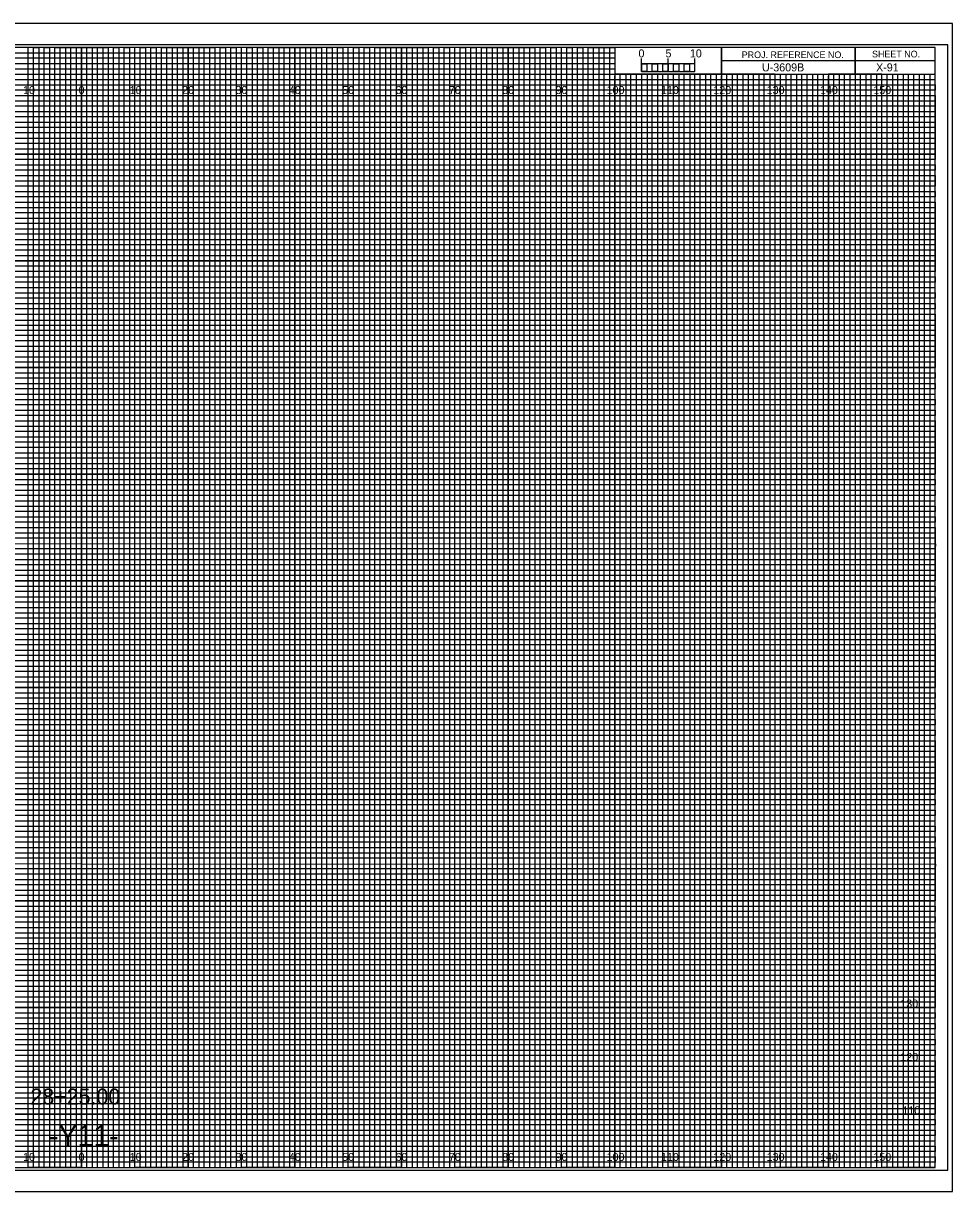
# Model space of a CAD drawing. Extents: x -13 to 323, y -5 to 3294.
# Drawn here: x 149.1 to 323.3, y 3075.5 to 3294.5 of the extents above; entities that cross this region are included whole.
import ezdxf

# ---------------------------------------------------------------- set-up
doc = ezdxf.new("R2010")
doc.units = 0
for name, color, linetype in [('Prop XS Alignment Label', 7, 'Continuous'), ('Prop XS Bar Scale Labels', 7, 'Continuous'), ('Prop XS Elevation Labels', 7, 'Continuous'), ('Prop XS Offset Labels', 7, 'Continuous'), ('Prop XS Project Number', 7, 'Continuous'), ('Prop XS Sheet Number', 7, 'Continuous'), ('Prop XS Station Labels', 7, 'Continuous'), ('Sheet Cross Section CELL', 7, 'Continuous'), ('Sheet Cross Section Grid Major CELL', 7, 'Continuous'), ('Sheet Cross Section Grid Middle CELL', 7, 'Continuous'), ('Sheet Cross Section Grid Minor 1 CELL', 7, 'Continuous'), ('Sheet Cross Section Grid Minor 2 CELL', 7, 'Continuous'), ('Sheet Cross Section Scale CELL', 7, 'Continuous'), ('Sheet Cutting Line CELL', 7, 'Continuous'), ('Sheet DOT Grid CELL', 7, 'Continuous'), ('Sheet Plot Border Inside CELL', 7, 'Continuous'), ('Sheet Plot Border Outside CELL', 7, 'Continuous')]:
    doc.layers.add(name, color=color, linetype=linetype)

msp = doc.modelspace()

# ---------------------------------------------------------------- linework, layer by layer
at = {"layer": 'Sheet Cross Section CELL'}
for p, q in [((305, 3290), (305, 3285)), ((305, 3285), (305, 3290)), ((280, 3287.5), (280, 3285)), ((320, 3287.49), (280, 3287.49)), ((280, 3285), (320, 3285))]:
    msp.add_line(p, q, dxfattribs=at)
for points in [[(320, 3290), (0, 3290), (0, 3080), (320, 3080)], [(280, 3290), (260, 3290), (260, 3285.03), (280, 3285.03)], [(320, 3290), (280, 3290), (280, 3285), (320, 3285)]]:
    msp.add_lwpolyline(points, close=True, dxfattribs=at)
at = {"layer": 'Sheet Cross Section Grid Major CELL'}
for p, q in [((150, 3290), (140, 3290)), ((150, 3080), (150, 3290)), ((170, 3290), (160, 3290)), ((160, 3290), (160, 3080)), ((170, 3080), (170, 3290)), ((190, 3290), (180, 3290)), ((180, 3290), (180, 3080)), ((190, 3080), (190, 3290)), ((210, 3290), (200, 3290)), ((200, 3290), (200, 3080)), ((210, 3080), (210, 3290)), ((230, 3290), (220, 3290)), ((220, 3290), (220, 3080)), ((230, 3080), (230, 3290)), ((250, 3290), (240, 3290)), ((240, 3290), (240, 3080)), ((250, 3080), (250, 3290)), ((260, 3290), (260, 3080)), ((270, 3080), (270, 3285)), ((290, 3285), (280, 3285)), ((280, 3285), (280, 3080)), ((290, 3080), (290, 3285)), ((310, 3285), (300, 3285)), ((300, 3285), (300, 3080)), ((310, 3080), (310, 3285)), ((160, 3080), (150, 3080)), ((180, 3080), (170, 3080)), ((200, 3080), (190, 3080)), ((220, 3080), (210, 3080)), ((240, 3080), (230, 3080)), ((260, 3080), (250, 3080)), ((280, 3080), (270, 3080)), ((300, 3080), (290, 3080)), ((320, 3080), (310, 3080)), ((320, 3080), (320, 3080))]:
    msp.add_line(p, q, dxfattribs=at)
for points in [[(0, 3280), (320, 3280), (320, 3270), (0, 3270)], [(0, 3260), (320, 3260), (320, 3250), (0, 3250)], [(0, 3240), (320, 3240), (320, 3230), (0, 3230)], [(0, 3220), (320, 3220), (320, 3210), (0, 3210)], [(0, 3200), (320, 3200), (320, 3190), (0, 3190)], [(0, 3180), (320, 3180), (320, 3170), (0, 3170)], [(0, 3160), (320, 3160), (320, 3150), (0, 3150)], [(0, 3140), (320, 3140), (320, 3130), (0, 3130)], [(0, 3120), (320, 3120), (320, 3110), (0, 3110)], [(0, 3100), (320, 3100), (320, 3090), (0, 3090)]]:
    msp.add_lwpolyline(points, dxfattribs=at)
at = {"layer": 'Sheet Cross Section Grid Middle CELL'}
for points in [[(145, 3080), (155, 3080), (155, 3290), (165, 3290), (165, 3080), (175, 3080), (175, 3290), (185, 3290), (185, 3080), (195, 3080), (195, 3290), (205, 3290), (205, 3080), (215, 3080), (215, 3290), (225, 3290), (225, 3080), (235, 3080), (235, 3290), (245, 3290), (245, 3080), (255, 3080), (255, 3290), (259.93, 3290), (260, 3290), (260, 3285), (264.99, 3285), (264.99, 3080), (275, 3080), (275, 3285), (285, 3285), (285, 3080), (295, 3080), (295, 3285), (305, 3285), (305, 3080), (315, 3080), (315, 3285)], [(0, 3285), (275, 3285)], [(0, 3265), (320, 3265), (320, 3275), (0, 3275)], [(0, 3245), (320, 3245), (320, 3255), (0, 3255)], [(0, 3225), (320, 3225), (320, 3235), (0, 3235)], [(0, 3205), (320, 3205), (320, 3215), (0, 3215)], [(0, 3185), (320, 3185), (320, 3195), (0, 3195)], [(0, 3165), (320, 3165), (320, 3175), (0, 3175)], [(0, 3145), (320, 3145), (320, 3155), (0, 3155)], [(0, 3125), (320, 3125), (320, 3135), (0, 3135)], [(0, 3105), (320, 3105), (320, 3115), (0, 3115)], [(0, 3085), (320, 3085), (320, 3095), (0, 3095)]]:
    msp.add_lwpolyline(points, dxfattribs=at)
at = {"layer": 'Sheet Cross Section Grid Minor 1 CELL'}
for p, q in [((0, 3289), (260, 3289)), ((260, 3287.98), (0, 3287.98)), ((260, 3289), (260, 3287.98)), ((0, 3287), (260, 3287)), ((260, 3285.89), (0, 3285.89)), ((260, 3287), (260, 3285.89)), ((0, 3284), (320, 3284))]:
    msp.add_line(p, q, dxfattribs=at)
for points in [[(0, 3283), (270, 3283), (320, 3283), (320, 3282), (0, 3282)], [(0, 3281), (320, 3281), (320, 3279), (0, 3279)], [(0, 3278), (320, 3278), (320, 3277), (0, 3276.98)], [(0, 3276), (320, 3276), (320, 3274), (0, 3274)], [(0, 3273), (320, 3273), (320, 3272), (0, 3272)], [(0, 3271), (320, 3271), (320, 3269), (0, 3269)], [(0, 3268), (320, 3268), (320, 3267), (0, 3267)], [(0, 3266), (320, 3266), (320, 3264), (0, 3264)], [(0, 3263), (320, 3263), (320, 3262), (0, 3262)], [(0, 3261), (320, 3261), (320, 3259), (0, 3259)], [(0, 3258), (320, 3258), (320, 3257), (0, 3257)], [(0, 3256), (320, 3256), (320, 3253.95), (320, 3253), (320, 3252), (0, 3252)], [(0, 3254), (320, 3254), (320, 3253), (0, 3253)], [(0, 3251), (320, 3251), (320, 3249), (0, 3249.03)], [(0, 3249.03), (320, 3249), (320, 3248), (0, 3248)], [(0, 3247), (320, 3247), (320, 3246), (0, 3246)], [(0, 3244), (320, 3244), (320, 3243), (0, 3243)], [(0, 3242), (320, 3242), (320, 3241), (0, 3241)], [(-0.07, 3238.89), (320, 3238.89), (320, 3237.88), (-0.07, 3237.88)], [(0, 3237), (320, 3237), (320, 3236), (0, 3236)], [(0, 3234), (320, 3234), (320, 3233), (0, 3233)], [(0, 3232), (320, 3232), (320, 3231), (0, 3231)], [(0, 3229), (320, 3229), (320, 3228), (0, 3228)], [(0, 3227), (320, 3227), (320, 3226), (0, 3226)], [(0, 3224), (320, 3224), (320, 3223), (0, 3223)], [(0, 3222), (320, 3222), (320, 3221), (0, 3221)], [(0, 3219), (320, 3219), (319.99, 3217.98), (0, 3218)], [(0, 3217), (320, 3217), (320, 3216), (0, 3216)], [(0, 3214), (320, 3214), (320, 3213), (0, 3213)], [(0, 3212), (320, 3212), (320, 3211), (0, 3211)], [(0, 3209), (320, 3209), (320, 3208), (0, 3208)], [(0, 3207), (320, 3207), (320, 3206), (0, 3206)], [(0, 3204), (320, 3204), (320, 3203), (0, 3203)], [(0, 3202), (320, 3202), (320, 3201), (0, 3201)], [(0, 3199), (320, 3199), (320, 3198), (0, 3198)], [(0, 3196.99), (320.07, 3196.91), (320, 3196), (0, 3196)], [(0, 3194), (320, 3194), (320, 3193), (0, 3193)], [(0, 3192), (320, 3192), (320, 3191), (0, 3191)], [(0, 3189), (320, 3189), (320, 3188), (0, 3188)], [(0, 3187), (320, 3187), (320, 3186), (0, 3186)], [(0, 3184), (320, 3184), (320, 3183), (0, 3183)], [(0, 3182), (320, 3182), (320, 3181), (0, 3181)], [(0, 3179), (320, 3179), (320, 3178), (0, 3178)], [(0, 3177), (320, 3177), (320, 3176), (0, 3176)], [(0, 3174), (320, 3174), (320, 3173), (0, 3173)], [(0, 3172), (320, 3172), (320, 3171), (0, 3171)], [(0, 3169), (320, 3169), (320, 3168), (0, 3168)], [(0, 3167), (320, 3167), (320, 3166), (0, 3166)], [(0, 3164), (320, 3164), (320, 3163), (0, 3163)], [(0, 3162), (320, 3162), (320, 3161), (0, 3161)], [(0, 3159), (320, 3159), (319.99, 3157.98), (0, 3158)], [(0, 3157), (320, 3157), (320, 3156), (0, 3156)], [(0, 3154), (320, 3154), (320, 3153), (0, 3153)], [(0, 3152), (320, 3152), (320, 3151), (0, 3151)], [(0, 3149), (320, 3149), (320, 3148), (0, 3148)], [(0, 3147), (320, 3147), (320, 3146), (0, 3146)], [(0, 3144), (320, 3144), (320, 3143), (0, 3143)], [(0, 3142), (320, 3142), (320, 3141), (0, 3141)], [(0, 3139), (320, 3139), (320, 3138), (0, 3138)], [(0, 3136.99), (320.07, 3136.91), (320, 3136), (0, 3136)], [(0, 3134), (320, 3134), (320, 3133), (0, 3133)], [(0, 3132), (320, 3132), (320, 3131), (0, 3131)], [(0, 3129), (320, 3129), (320, 3128), (0, 3128)], [(0, 3127), (320, 3127), (320, 3126), (0, 3126)], [(0, 3124), (320, 3124), (320, 3123), (0, 3123)], [(0, 3122), (320, 3122), (320, 3121), (0, 3121)], [(0, 3119), (320, 3119), (320, 3118), (0, 3118)], [(0, 3117), (320, 3117), (320, 3116), (0, 3116)], [(0, 3114), (320, 3114), (320, 3113), (0, 3113)], [(0, 3112), (320, 3112), (320, 3111), (0, 3111)], [(0, 3109), (320, 3109), (320, 3108), (0, 3108)], [(0, 3107), (320, 3107), (320, 3106), (0, 3106)], [(0, 3104), (320, 3104), (320, 3103), (0, 3103)], [(0, 3102), (320, 3102), (320, 3101), (0, 3101)], [(0, 3099), (320, 3099), (320, 3098), (0, 3098)], [(0, 3097), (320, 3097), (320, 3096), (0, 3096)], [(0, 3094), (320, 3094), (320, 3093), (0, 3093)], [(0, 3092), (320, 3092), (320, 3091), (0, 3091)], [(0, 3089), (320, 3089), (320, 3088), (0, 3088)], [(0, 3087), (320, 3087), (320, 3086), (0, 3086)], [(0, 3084), (320, 3084), (320, 3083), (0, 3083)], [(0, 3082), (320, 3082), (320, 3081), (0, 3081)]]:
    msp.add_lwpolyline(points, dxfattribs=at)
at = {"layer": 'Sheet Cross Section Grid Minor 2 CELL'}
for p, q in [((267, 3285), (266.01, 3285)), ((266.01, 3285), (266.01, 3080)), ((267, 3080), (267, 3285)), ((269, 3285), (268, 3285)), ((268, 3285), (268, 3080)), ((269, 3080), (269, 3285)), ((266.01, 3080), (265, 3080)), ((268, 3080), (267, 3080))]:
    msp.add_line(p, q, dxfattribs=at)
for points in [[(150, 3080), (151, 3080), (151, 3290), (152, 3290), (152, 3080)], [(152, 3080), (153, 3080), (153, 3290), (154, 3290), (154, 3080)], [(155, 3080), (156, 3080), (156, 3290), (157, 3290), (157, 3080)], [(157, 3080), (158, 3080), (158, 3290), (159, 3290), (159, 3080)], [(160, 3080), (161, 3080), (161, 3290), (162, 3290), (162, 3080)], [(162, 3080), (163, 3080), (163, 3290), (164, 3290), (164, 3080)], [(165, 3080), (166, 3080), (166, 3290), (167, 3290), (167, 3080)], [(167, 3080), (168, 3080), (168, 3290), (169, 3290), (169, 3080)], [(170, 3080), (171, 3080), (171, 3290), (172, 3290), (172, 3080)], [(172, 3080), (173, 3080), (173, 3290), (174, 3290), (174, 3080)], [(175, 3080), (176, 3080), (176, 3290), (177, 3290), (177, 3080)], [(177, 3080), (178, 3080), (178, 3290), (179, 3290), (179, 3080)], [(180, 3080), (181, 3080), (181, 3290), (182, 3290), (182, 3080)], [(182, 3080), (183, 3080), (183, 3290), (184, 3290), (184, 3080)], [(185, 3080), (186, 3080), (186, 3290), (187, 3290), (187, 3080)], [(187, 3080), (188, 3080), (188, 3290), (189, 3290), (189, 3080)], [(190, 3080), (191, 3080), (191, 3290), (192, 3290), (192, 3080)], [(192, 3080), (193, 3080), (193, 3290), (194, 3290), (194, 3080)], [(195, 3080), (196, 3080), (196, 3290), (197, 3290), (197, 3080)], [(197, 3080), (198, 3080), (198, 3290), (199, 3290), (199, 3080)], [(200, 3080), (201, 3080), (201, 3290), (202, 3290), (202, 3080)], [(202, 3080), (203, 3080), (203, 3290), (204, 3290), (204, 3080)], [(205, 3080), (206, 3080), (206, 3290), (207, 3290), (207, 3080)], [(207, 3080), (208, 3080), (208, 3290), (209, 3290), (209, 3080)], [(210, 3080), (211, 3080), (211, 3290), (212, 3290), (212, 3080)], [(212, 3080), (213, 3080), (213, 3290), (214, 3290), (214, 3080)], [(215, 3080), (216, 3080), (216, 3290), (217, 3290), (217, 3080)], [(217, 3080), (218, 3080), (218, 3290), (219, 3290), (219, 3080)], [(220, 3080), (221, 3080), (221, 3290), (222, 3290), (222, 3080)], [(222, 3080), (223, 3080), (223, 3290), (224, 3290), (224, 3080)], [(225, 3080), (226, 3080), (226, 3290), (227, 3290), (227, 3080)], [(227, 3080), (228, 3080), (228, 3290), (229, 3290), (229, 3080)], [(230, 3080), (231, 3080), (231, 3290), (232, 3290), (232, 3080)], [(232, 3080), (233, 3080), (233, 3290), (234, 3290), (234, 3080)], [(235, 3080), (236, 3080), (236, 3290), (237, 3290), (237, 3080)], [(237, 3080), (238, 3080), (238, 3290), (239, 3290), (239, 3080)], [(240, 3080), (241, 3080), (241, 3290), (242, 3290), (242, 3080)], [(242, 3080), (243, 3080), (243, 3290), (244, 3290), (244, 3080)], [(245, 3080), (246, 3080), (246, 3290), (247, 3290), (247, 3080)], [(247, 3080), (248, 3080), (248, 3290), (249, 3290), (249, 3080)], [(250, 3080), (251, 3080), (251, 3290), (252, 3290), (252, 3080)], [(252, 3080), (253, 3080), (253, 3290), (254, 3290), (254, 3080)], [(255, 3080), (256, 3080), (256, 3290), (257, 3290), (257, 3080)], [(257, 3080), (258, 3080), (258, 3290), (259, 3290), (259, 3080)], [(260, 3080), (261, 3080), (261, 3285), (262.02, 3285), (262.02, 3080)], [(262, 3080), (263, 3080), (263, 3285), (263.99, 3285), (263.99, 3080)], [(270, 3080), (270.98, 3080), (270.98, 3285), (272, 3285), (272, 3080)], [(272, 3080), (273, 3080), (273, 3285), (274.05, 3285), (274.05, 3080)], [(275, 3080), (276, 3080), (276, 3285), (277, 3285), (277, 3080)], [(277, 3080), (278, 3080), (278, 3285), (279, 3285), (279, 3080)], [(280, 3080), (281, 3080), (281, 3285), (282, 3285), (282, 3080)], [(282, 3080), (283, 3080), (283, 3285), (284, 3285), (284, 3080)], [(285, 3080), (286, 3080), (286, 3285), (287, 3285), (287, 3080)], [(287, 3080), (288, 3080), (288, 3285), (289, 3285), (289, 3080)], [(290, 3080), (291, 3080), (291, 3285), (292, 3285), (292, 3080)], [(292, 3080), (293, 3080), (293, 3285), (294, 3285), (294, 3080)], [(295, 3080), (296, 3080), (296, 3285), (297, 3285), (297, 3080)], [(297, 3080), (298, 3080), (298, 3285), (299, 3285), (299, 3080)], [(300, 3080), (301, 3080), (301, 3285), (302, 3285), (302, 3080)], [(302, 3080), (303, 3080), (303, 3285), (304, 3285), (304, 3080)], [(305, 3080), (306, 3080), (306, 3285), (307, 3285), (307, 3080)], [(307, 3080), (308, 3080), (308, 3285), (309, 3285), (309, 3080)], [(310, 3080), (311, 3080), (311, 3285), (312, 3285), (312, 3080)], [(312, 3080), (313, 3080), (313, 3285), (314, 3285), (314, 3080)], [(315, 3080), (316, 3080), (316, 3285), (317, 3285), (317, 3080)], [(317, 3080), (318, 3080), (318, 3285), (319, 3285), (319, 3080)]]:
    msp.add_lwpolyline(points, dxfattribs=at)
at = {"layer": 'Sheet Cross Section Scale CELL'}
for p, q in [((265, 3285.49), (265, 3287.9)), ((265, 3286.9), (265, 3287.9)), ((270, 3285.49), (270, 3287.9)), ((275, 3285.49), (275, 3287.9)), ((275, 3286.9), (275, 3287.9))]:
    msp.add_line(p, q, dxfattribs=at)
for points in [[(275, 3286.9), (265, 3286.9), (265, 3285.49), (275, 3285.49)], [(265, 3286.9), (266, 3286.9), (266, 3285.49), (265, 3285.49)], [(267, 3286.9), (268, 3286.9), (268, 3285.49), (267, 3285.49)], [(269, 3286.9), (270, 3286.9), (270, 3285.49), (269, 3285.49)], [(271, 3286.9), (272, 3286.9), (272, 3285.49), (271, 3285.49)], [(273, 3286.9), (274, 3286.9), (274, 3285.49), (273, 3285.49)]]:
    msp.add_lwpolyline(points, close=True, dxfattribs=at)
at = {"layer": 'Sheet Cutting Line CELL'}
for p, q in [((323.3, 3294.5), (-13.4, 3294.5)), ((-13.4, 3075.5), (323.3, 3075.5))]:
    msp.add_line(p, q, dxfattribs=at)
at = {"layer": 'Sheet DOT Grid CELL'}
for p, q in [((150, 3080), (150, 3290)), ((160, 3080), (160, 3290)), ((170, 3080), (170, 3290)), ((180, 3080), (180, 3290)), ((190, 3080), (190, 3290)), ((200, 3080), (200, 3290)), ((210, 3080), (210, 3290)), ((220, 3080), (220, 3290)), ((230, 3080), (230, 3290)), ((240, 3080), (240, 3290)), ((250, 3080), (250, 3290)), ((260, 3080), (260, 3284.69)), ((270, 3080), (270, 3284.69)), ((280, 3080), (280, 3284.69)), ((290, 3080), (290, 3284.69)), ((300, 3080), (300, 3284.69)), ((310, 3080), (310, 3284.69)), ((0, 3280), (320, 3280)), ((0, 3270), (320, 3270)), ((0, 3260), (320, 3260)), ((0, 3250), (320, 3250)), ((0, 3240), (320, 3240)), ((0, 3230), (320, 3230)), ((0, 3220), (320, 3220)), ((0, 3210), (320, 3210)), ((0, 3200), (320, 3200)), ((0, 3190), (320, 3190)), ((0, 3180), (320, 3180)), ((0, 3170), (320, 3170)), ((0, 3160), (320, 3160)), ((0, 3150), (320, 3150)), ((0, 3140), (320, 3140)), ((0, 3130), (320, 3130)), ((0, 3120), (320, 3120)), ((0, 3110), (320, 3110)), ((0, 3100), (320, 3100)), ((0, 3090), (320, 3090))]:
    msp.add_line(p, q, dxfattribs=at)
at = {"layer": 'Sheet Plot Border Inside CELL'}
msp.add_lwpolyline([(-10.8, 3079.5), (322.4, 3079.5), (322.4, 3290.5), (-10.8, 3290.5)], close=True, dxfattribs=at)
at = {"layer": 'Sheet Plot Border Outside CELL'}
msp.add_lwpolyline([(-13.4, 3075.5), (323.3, 3075.5), (323.3, 3294.5), (-13.4, 3294.5)], close=True, dxfattribs=at)

# ---------------------------------------------------------------- texts
at = {"layer": 'Prop XS Alignment Label'}
msp.add_text('-Y11-', height=4, dxfattribs=at).set_placement((153.89, 3084))
at = {"layer": 'Prop XS Bar Scale Labels'}
for s, p in [('5', (269.47, 3288.12)), ('10', (274.04, 3288.12))]:
    msp.add_text(s, height=1.5, dxfattribs=at).set_placement(p)
at = {"layer": 'Prop XS Elevation Labels'}
for s, p in [('130', (313.49, 3110)), ('120', (313.5, 3100)), ('110', (313.88, 3090))]:
    msp.add_text(s, height=1.5, dxfattribs=at).set_placement(p)
at = {"layer": 'Prop XS Offset Labels'}
for s, p in [('10', (149.04, 3281.25)), ('0', (159.45, 3281.25)), ('0', (159.45, 3281.25)), ('10', (169.04, 3281.25)), ('20', (178.86, 3281.25)), ('30', (188.86, 3281.25)), ('40', (198.86, 3281.25)), ('50', (208.86, 3281.25)), ('60', (218.86, 3281.25)), ('70', (228.86, 3281.25)), ('80', (238.86, 3281.25)), ('90', (248.86, 3281.25)), ('100', (258.44, 3281.25)), ('110', (268.62, 3281.25)), ('120', (278.44, 3281.25)), ('130', (288.44, 3281.25)), ('140', (298.44, 3281.25)), ('150', (308.44, 3281.25)), ('10', (149.04, 3081.25)), ('0', (159.45, 3081.25)), ('0', (159.45, 3081.25)), ('10', (169.04, 3081.25)), ('20', (178.86, 3081.25)), ('30', (188.86, 3081.25)), ('40', (198.86, 3081.25)), ('50', (208.86, 3081.25)), ('60', (218.86, 3081.25)), ('70', (228.86, 3081.25)), ('80', (238.86, 3081.25)), ('90', (248.86, 3081.25)), ('100', (258.44, 3081.25)), ('110', (268.62, 3081.25)), ('120', (278.44, 3081.25)), ('130', (288.44, 3081.25)), ('140', (298.44, 3081.25)), ('150', (308.44, 3081.25))]:
    msp.add_text(s, height=1.5, dxfattribs=at).set_placement(p)
at = {"layer": 'Prop XS Project Number'}
msp.add_text('U-3609B', height=1.5, dxfattribs=at).set_placement((287.56, 3285.5))
at = {"layer": 'Prop XS Sheet Number'}
msp.add_text('X-91', height=1.5, dxfattribs=at).set_placement((308.95, 3285.5))
at = {"layer": 'Prop XS Station Labels'}
msp.add_text('28+25.00', height=3, dxfattribs=at).set_placement((150.41, 3091.82))
at = {"layer": 'Sheet Cross Section CELL'}
for s, p in [('SHEET NO.', (308.19, 3288.12)), ('PROJ. REFERENCE NO.', (283.77, 3287.99))]:
    msp.add_text(s, height=1.25, dxfattribs=at).set_placement(p)
at = {"layer": 'Sheet Cross Section Scale CELL'}
msp.add_text('0', height=1.5, dxfattribs=at).set_placement((264.41, 3288.12))

doc.saveas('drawing.dxf')
